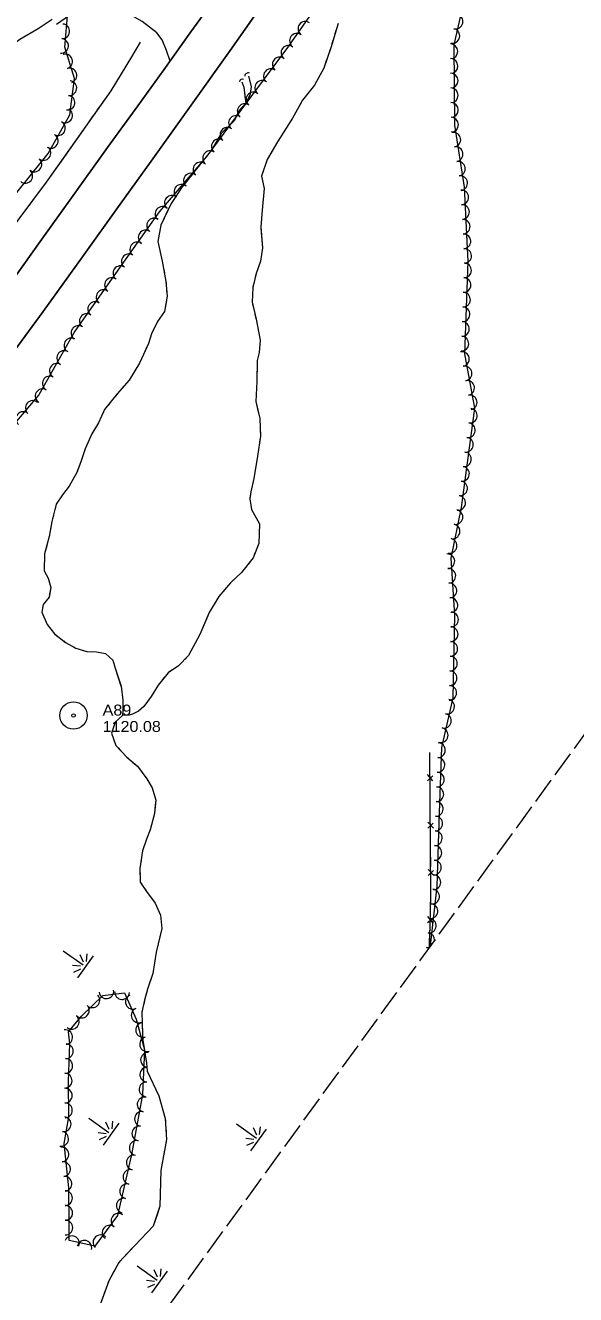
# Model space of a CAD drawing. Extents: x 297327 to 299792, y 46897 to 49095.
# Drawn here: x 298790 to 299091, y 47500 to 48196 of the extents above; entities that cross this region are included whole.
import ezdxf

# ---------------------------------------------------------------- set-up
doc = ezdxf.new("R2010")
doc.units = 0
doc.header["$LTSCALE"] = 2.4
doc.linetypes.add('LONG_DASHED', pattern=[7.5, 6, -1.5])
for name, color, linetype, lineweight in [('11', 7, 'Continuous', 25), ('15', 7, 'Continuous', 13), ('17', 7, 'LONG_DASHED', 13), ('18', 7, 'Continuous', 13), ('19', 7, 'Continuous', 13), ('4', 7, 'Continuous', 13), ('6', 7, 'Continuous', 13)]:
    doc.layers.add(name, color=color, linetype=linetype, lineweight=lineweight)

msp = doc.modelspace()

# ---------------------------------------------------------------- linework, layer by layer
at = {"layer": '11'}
for points in [[(298773.947, 48043.937), (298797.872, 48077.411), (298815.068, 48101.215), (298834.844, 48128.806), (298851.433, 48151.673), (298865.686, 48171.463), (298880.386, 48192.263), (298896.726, 48214.837)], [(298781.415, 48014.255), (298799.539, 48039.023), (298821.048, 48068.955), (298841.741, 48097.8), (298858.666, 48121.374), (298879.721, 48150.861), (298901.899, 48182.138), (298918.424, 48205.473)]]:
    msp.add_lwpolyline(points, dxfattribs=at)
at = {"layer": '15'}
for p, q in [((299011.49, 47786.643), (299011.405, 47797.194)), ((299013.152, 47781.603), (299010.105, 47785.043)), ((299010.132, 47781.737), (299013.066, 47784.367)), ((299011.615, 47771.229), (299011.54, 47780.509)), ((299011.7, 47760.679), (299011.615, 47771.229)), ((299013.362, 47755.639), (299010.315, 47759.078)), ((299010.342, 47755.773), (299013.276, 47758.402)), ((299011.825, 47745.265), (299011.75, 47754.544)), ((299011.91, 47734.714), (299011.825, 47745.265)), ((299013.572, 47729.674), (299010.525, 47733.114)), ((299010.552, 47729.808), (299013.486, 47732.438)), ((299011.728, 47708.753), (299012.022, 47719.3)), ((299010.194, 47703.899), (299013.221, 47706.422)), ((299013.207, 47703.657), (299010.286, 47707.204)), ((299011.271, 47690.502), (299011.338, 47693.344))]:
    msp.add_line(p, q, dxfattribs=at)
for points in [[(299011.271, 47690.502), (299011.545, 47702.188), (299012.032, 47719.673), (299011.405, 47797.194)], [(299012.022, 47719.3), (299012.032, 47719.673), (299011.96, 47728.58)], [(299011.338, 47693.344), (299011.545, 47702.188), (299011.557, 47702.621)]]:
    msp.add_lwpolyline(points, dxfattribs=at)
for centre, radius, start, end in [((298911.845, 48167.881), 1.876, 68.43566, 174.67523), ((298908.683, 48164.735), 1.626, 67.28803, 173.52759)]:
    msp.add_arc(centre, radius, start, end, dxfattribs=at)
at = {"layer": '17'}
for points in [[(298869.073, 48176.256), (298867.134, 48182.115), (298864.799, 48187.957), (298861.825, 48191.745), (298853.755, 48197.965), (298841.935, 48204.811), (298834.747, 48207.957), (298827.75, 48208.774), (298821.748, 48206.38), (298816.292, 48202.905), (298806.831, 48196.299)], [(298804.335, 48199.125), (298796.758, 48194.022), (298786.781, 48188.133), (298778.292, 48181.845), (298770.455, 48177.553)]]:
    msp.add_lwpolyline(points, dxfattribs=at)
at = {"layer": '18'}
for points in [[(299011.795, 47691.222), (299015.435, 47723.842), (299016.736, 47764.31), (299018.061, 47800.007), (299024.133, 47827.15), (299025.206, 47872.392), (299023.037, 47903.737), (299028.711, 47931.468), (299036.04, 47985.928), (299030.647, 48015.786), (299032.488, 48066.369), (299030.517, 48107.23), (299025.207, 48141.127), (299024.814, 48185.103), (299032.807, 48220.691), (299036.611, 48250.046), (299043.903, 48276.662), (299057.908, 48300.748), (299070.384, 48317.762), (299076.733, 48326.492)], [(298948.867, 48205.749), (298933.44, 48183.723), (298907.768, 48149.445), (298889.188, 48124.204), (298863.058, 48093.645), (298844.723, 48067.797), (298816.908, 48028.238), (298797.151, 47993.274), (298775.572, 47968.078)], [(298764.559, 48197.242), (298760.904, 48170.711), (298762.442, 48144.645), (298760.665, 48123.823), (298759.649, 48104.523), (298756.703, 48095.82), (298757.654, 48091.129), (298770.724, 48090.882), (298784.392, 48103.366), (298802.216, 48125.633), (298814.147, 48146.778), (298816.652, 48166.779), (298811.357, 48183.936), (298812.99, 48203.324)]]:
    msp.add_lwpolyline(points, dxfattribs=at)
msp.add_lwpolyline([(298814.192, 47637.368), (298813.318, 47644.049), (298820.452, 47652.591), (298832.182, 47663.884), (298844.16, 47665.439), (298850.429, 47651.003), (298855.11, 47634.11), (298853.896, 47609.629), (298847.959, 47576.761), (298840.282, 47543.394), (298827.783, 47526.519), (298813.673, 47529.645), (298813.759, 47537.868), (298813.561, 47558.415), (298811.04, 47582.814), (298813.583, 47597.512), (298813.402, 47616.899)], close=True, dxfattribs=at)
for centre, radius, start, end in [((298943.188, 48193.988), 4.004, 55.00028, 234.98496), ((299025.533, 48197.91), 4.023, 257.34919, 77.33387), ((298809.977, 48192.584), 4.014, 265.19315, 85.17783), ((298938.594, 48187.429), 4.004, 55.00028, 234.98496), ((299023.77, 48190.061), 4.023, 257.34919, 77.33387), ((298809.303, 48184.585), 4.014, 265.19315, 85.17783), ((298933.91, 48180.854), 4.004, 53.17683, 233.16151), ((299022.739, 48181.649), 4.023, 270.51968, 90.50436), ((298811.577, 48176.1), 4.014, 287.15895, 107.14363), ((298929.11, 48174.445), 4.004, 53.17683, 233.16151), ((299022.811, 48173.605), 4.023, 270.51968, 90.50436), ((298813.944, 48168.43), 4.014, 287.15895, 107.14363), ((298924.31, 48168.036), 4.004, 53.17683, 233.16151), ((299022.883, 48165.561), 4.023, 270.51968, 90.50436), ((298813.865, 48161.433), 4.014, 262.86889, 82.85357), ((298919.51, 48161.627), 4.004, 53.17683, 233.16151), ((298812.868, 48153.468), 4.014, 262.86889, 82.85357), ((298914.71, 48155.218), 4.004, 53.17683, 233.16151), ((299022.955, 48157.517), 4.023, 270.51968, 90.50436), ((298811.556, 48146.462), 4.014, 240.57393, 60.55861), ((298909.91, 48148.809), 4.004, 53.17683, 233.16151), ((299023.027, 48149.473), 4.023, 270.51968, 90.50436), ((298807.612, 48139.471), 4.014, 240.57393, 60.55861), ((298905.168, 48142.378), 4.004, 53.65073, 233.63541), ((299023.099, 48141.429), 4.023, 270.51968, 90.50436), ((298803.667, 48132.48), 4.014, 240.57393, 60.55861), ((298900.421, 48135.929), 4.004, 53.65073, 233.63541), ((299024.322, 48133.171), 4.023, 278.91075, 98.89543), ((298799.732, 48125.891), 4.014, 231.33154, 51.31622), ((298895.675, 48129.481), 4.004, 53.65073, 233.63541), ((299025.567, 48125.224), 4.023, 278.91075, 98.89543), ((298794.716, 48119.625), 4.014, 231.33154, 51.31622), ((298885.634, 48116.823), 4.004, 49.47499, 229.45967), ((298890.928, 48123.032), 4.004, 53.65073, 233.63541), ((299026.812, 48117.277), 4.023, 278.91075, 98.89543), ((298789.699, 48113.358), 4.014, 231.33154, 51.31622), ((298880.43, 48110.737), 4.004, 49.47499, 229.45967), ((298875.227, 48104.651), 4.004, 49.47499, 229.45967), ((299028.057, 48109.329), 4.023, 278.91075, 98.89543), ((298870.023, 48098.566), 4.004, 49.47499, 229.45967), ((299028.683, 48101.546), 4.023, 272.76928, 92.75396), ((298864.819, 48092.48), 4.004, 49.47499, 229.45967), ((299029.071, 48093.511), 4.023, 272.76928, 92.75396), ((298860.284, 48086.113), 4.004, 54.65809, 234.64277), ((299029.459, 48085.476), 4.023, 272.76928, 92.75396), ((298855.652, 48079.582), 4.004, 54.65809, 234.64277), ((299029.846, 48077.441), 4.023, 272.76928, 92.75396), ((298851.019, 48073.051), 4.004, 54.65809, 234.64277), ((299030.234, 48069.406), 4.023, 272.76928, 92.75396), ((298846.392, 48066.527), 4.004, 54.89558, 234.88025), ((299030.206, 48061.547), 4.023, 267.92327, 87.90794), ((298841.786, 48059.976), 4.004, 54.89558, 234.88025), ((298837.18, 48053.426), 4.004, 54.89558, 234.88025), ((299029.913, 48053.508), 4.023, 267.92327, 87.90794), ((298827.969, 48040.326), 4.004, 54.89558, 234.88025), ((298832.575, 48046.876), 4.004, 54.89558, 234.88025), ((299029.621, 48045.469), 4.023, 267.92327, 87.90794), ((298823.364, 48033.776), 4.004, 54.89558, 234.88025), ((299029.328, 48037.43), 4.023, 267.92327, 87.90794), ((298818.758, 48027.226), 4.004, 54.89558, 234.88025), ((299029.035, 48029.391), 4.023, 267.92327, 87.90794), ((298814.909, 48020.441), 4.004, 60.53831, 240.52298), ((299028.743, 48021.352), 4.023, 267.92327, 87.90794), ((298810.97, 48013.47), 4.004, 60.53831, 240.52298), ((299029.029, 48012.902), 4.023, 280.24613, 100.23081), ((298807.031, 48006.499), 4.004, 60.53831, 240.52298), ((298803.092, 47999.528), 4.004, 60.53831, 240.52298), ((299030.458, 48004.986), 4.023, 280.24613, 100.23081), ((298799.153, 47992.556), 4.004, 60.53831, 240.52298), ((299031.888, 47997.069), 4.023, 280.24613, 100.23081), ((298793.768, 47986.102), 4.004, 49.42941, 229.41409), ((299033.318, 47989.153), 4.023, 280.24613, 100.23081), ((298788.56, 47980.021), 4.004, 49.42941, 229.41409), ((299033.368, 47981.862), 4.023, 262.34308, 82.32776), ((299032.296, 47973.889), 4.023, 262.34308, 82.32776), ((299031.223, 47965.917), 4.023, 262.34308, 82.32776), ((299030.15, 47957.945), 4.023, 262.34308, 82.32776), ((299029.077, 47949.972), 4.023, 262.34308, 82.32776), ((299028.004, 47942), 4.023, 262.34308, 82.32776), ((299026.931, 47934.028), 4.023, 262.34308, 82.32776), ((299025.497, 47926.262), 4.023, 258.44406, 78.42874), ((299023.884, 47918.381), 4.023, 258.44406, 78.42874), ((299022.272, 47910.5), 4.023, 258.44406, 78.42874), ((299021.045, 47902.023), 4.023, 273.96608, 93.95076), ((299021.6, 47893.998), 4.023, 273.96608, 93.95076), ((299022.156, 47885.973), 4.023, 273.96608, 93.95076), ((299022.711, 47877.948), 4.023, 273.96608, 93.95076), ((299023.046, 47870.114), 4.023, 268.64904, 88.63372), ((299022.855, 47862.072), 4.023, 268.64904, 88.63372), ((299022.665, 47854.03), 4.023, 268.64904, 88.63372), ((299022.474, 47845.988), 4.023, 268.64904, 88.63372), ((299022.283, 47837.946), 4.023, 268.64904, 88.63372), ((299022.092, 47829.904), 4.023, 268.64904, 88.63372), ((299020.913, 47822.399), 4.023, 257.39797, 77.38265), ((299019.157, 47814.549), 4.023, 257.39797, 77.38265), ((299017.401, 47806.699), 4.023, 257.39797, 77.38265), ((299015.896, 47798.428), 4.023, 267.88194, 87.86661), ((299015.597, 47790.389), 4.023, 267.88194, 87.86661), ((299015.299, 47782.351), 4.023, 267.88194, 87.86661), ((299015, 47774.312), 4.023, 267.88194, 87.86661), ((299014.702, 47766.273), 4.023, 267.88194, 87.86661), ((299014.434, 47758.223), 4.023, 268.1663, 88.15098), ((299014.175, 47750.183), 4.023, 268.1663, 88.15098), ((299013.917, 47742.143), 4.023, 268.1663, 88.15098), ((299013.658, 47734.103), 4.023, 268.1663, 88.15098), ((299013.4, 47726.063), 4.023, 268.1663, 88.15098), ((299012.689, 47718.222), 4.023, 263.64058, 83.62526), ((299011.797, 47710.227), 4.023, 263.64058, 83.62526), ((299010.905, 47702.233), 4.023, 263.64058, 83.62526), ((299010.013, 47694.238), 4.023, 0.91146, 83.62526), ((299010.013, 47694.238), 4.023, 263.64058, 287.03077), ((299009.121, 47686.244), 4.023, 64.94569, 83.62526), ((298826.491, 47661.341), 4.041, 223.92026, 43.90494), ((298834.11, 47666.267), 4.041, 187.40451, 7.38919), ((298842.756, 47665.841), 4.041, 177.40451, 357.38919), ((298848.611, 47660.5), 4.041, 113.48112, 293.46579), ((298820.669, 47655.736), 4.041, 223.92026, 43.90494), ((298851.83, 47653.087), 4.041, 113.48112, 293.46579), ((298815.146, 47649.538), 4.041, 230.14013, 50.12481), ((298854.264, 47645.084), 4.041, 105.49556, 285.48023), ((298811.57, 47641.101), 4.041, 277.4607, 97.44538), ((298856.422, 47637.296), 4.041, 105.49556, 285.48023), ((298811.923, 47633.412), 4.041, 267.79743, 87.78211), ((298811.611, 47625.337), 4.041, 267.79743, 87.78211), ((298856.957, 47628.65), 4.041, 87.16872, 267.1534), ((298811.299, 47617.261), 4.041, 267.79743, 87.78211), ((298856.557, 47620.578), 4.041, 87.16872, 267.1534), ((298811.36, 47609.078), 4.041, 270.54257, 90.52725), ((298856.156, 47612.506), 4.041, 87.16872, 267.1534), ((298855.072, 47604.238), 4.041, 79.76864, 259.75332), ((298811.435, 47600.997), 4.041, 270.54257, 90.52725), ((298853.635, 47596.285), 4.041, 79.76864, 259.75332), ((298810.719, 47593.363), 4.041, 260.19171, 80.17639), ((298852.198, 47588.332), 4.041, 79.76864, 259.75332), ((298809.341, 47585.399), 4.041, 260.19171, 80.17639), ((298809.535, 47576.804), 4.041, 275.90675, 95.89143), ((298850.762, 47580.379), 4.041, 79.76864, 259.75332), ((298810.365, 47568.765), 4.041, 275.90675, 95.89143), ((298849.118, 47572.366), 4.041, 77.05067, 257.03535), ((298811.196, 47560.726), 4.041, 275.90675, 95.89143), ((298847.306, 47564.49), 4.041, 77.05067, 257.03535), ((298845.494, 47556.614), 4.041, 77.05067, 257.03535), ((298811.499, 47552.855), 4.041, 270.55977, 90.54445), ((298843.682, 47548.738), 4.041, 77.05067, 257.03535), ((298811.577, 47544.773), 4.041, 270.55977, 90.54445), ((298840.725, 47540.439), 4.041, 53.481, 233.46568), ((298811.632, 47536.735), 4.041, 269.40846, 89.39314), ((298835.915, 47533.944), 4.041, 53.481, 233.46568), ((298815.338, 47528.096), 4.041, 337.51584, 157.50051), ((298822.096, 47525.613), 4.041, 347.51584, 167.50051), ((298830.895, 47528.647), 4.041, 43.481, 223.46568)]:
    msp.add_arc(centre, radius, start, end, dxfattribs=at)
at = {"layer": '19'}
for p, q in [((298959.977, 48192.979), (298959.435, 48191.183)), ((298958.349, 48187.589), (298957.806, 48185.793)), ((298956.677, 48182.214), (298956.074, 48180.437)), ((298912.505, 48157.25), (298912.215, 48156.642)), ((298829.146, 48149.292), (298830.234, 48150.823)), ((298832.411, 48153.887), (298833.499, 48155.418)), ((298911.637, 48155.425), (298911.349, 48154.816)), ((298888.958, 48123.914), (298887.769, 48122.434)), ((298925.106, 48127.141), (298924.175, 48125.511)), ((298920.503, 48116.921), (298919.9, 48115.143)), ((298791.988, 48097.338), (298793.116, 48098.84)), ((298865.572, 48061.982), (298865.915, 48060.116)), ((298914.901, 48054.241), (298914.477, 48052.413)), ((298867.176, 48050.723), (298867.339, 48048.833)), ((298914.246, 48048.673), (298914.161, 48046.798)), ((298914.302, 48043.077), (298914.731, 48041.25)), ((298836.405, 47989.299), (298835.213, 47987.822)), ((298839.981, 47993.73), (298838.789, 47992.253)), ((298832.922, 47984.811), (298832.135, 47983.084)), ((298918.256, 47980.147), (298918.32, 47978.272)), ((298918.45, 47974.522), (298918.514, 47972.647)), ((298918.336, 47968.915), (298918.072, 47967.059)), ((298805.126, 47927.113), (298804.657, 47925.275)), ((298803.894, 47921.559), (298803.567, 47919.69)), ((298915.867, 47907.23), (298915.19, 47905.48)), ((298913.307, 47902.282), (298912.142, 47900.81)), ((298909.812, 47897.867), (298908.647, 47896.396)), ((298815.625, 47855.405), (298817.274, 47854.465)), ((298820.901, 47853.355), (298822.717, 47852.806)), ((298865.974, 47838.44), (298864.801, 47836.974)), ((298870.019, 47842.256), (298868.452, 47841.223)), ((298838.01, 47804.712), (298838.65, 47802.925)), ((298840.562, 47799.739), (298841.864, 47798.358)), ((298853.178, 47738.02), (298852.876, 47736.146)), ((298852.517, 47732.383), (298852.582, 47730.486)), ((298810.524, 47688.505), (298821.437, 47680.695)), ((298818.457, 47673.697), (298827.068, 47685.728)), ((298821.643, 47682.306), (298819.792, 47686.336)), ((298823.488, 47686.869), (298823.043, 47682.656)), ((298820.01, 47680.025), (298815.599, 47680.477)), ((298816.286, 47676.806), (298820.13, 47678.586)), ((298856.484, 47666.5), (298856.002, 47664.665)), ((298855.047, 47660.992), (298854.624, 47659.142)), ((298824.601, 47596.668), (298835.514, 47588.858)), ((298832.534, 47581.86), (298841.145, 47593.891)), ((298835.72, 47590.469), (298833.869, 47594.499)), ((298837.565, 47595.032), (298837.12, 47590.819)), ((298905.445, 47593.522), (298916.358, 47585.712)), ((298918.409, 47591.886), (298917.964, 47587.673)), ((298834.087, 47588.188), (298829.676, 47588.64)), ((298830.363, 47584.969), (298834.207, 47586.749)), ((298866.709, 47591.131), (298866.834, 47589.12)), ((298914.931, 47585.042), (298910.52, 47585.494)), ((298913.378, 47578.714), (298921.989, 47590.745)), ((298916.564, 47587.323), (298914.713, 47591.353)), ((298866.005, 47579.154), (298865.632, 47577.174)), ((298911.207, 47581.823), (298915.051, 47583.603)), ((298851.044, 47515.671), (298861.957, 47507.861)), ((298838.682, 47513.54), (298837.718, 47511.771)), ((298858.977, 47500.863), (298867.588, 47512.894)), ((298862.163, 47509.472), (298860.312, 47513.502)), ((298864.008, 47514.035), (298863.563, 47509.822)), ((298860.53, 47507.191), (298856.119, 47507.643)), ((298856.806, 47503.972), (298860.65, 47505.752))]:
    msp.add_line(p, q, dxfattribs=at)
for points in [[(298961.166, 48196.914), (298957.122, 48183.527), (298953.349, 48172.398), (298948.134, 48163.049), (298941.658, 48154.796), (298936.091, 48144.931), (298927.903, 48132.038), (298922.307, 48122.241), (298919.24, 48113.196), (298920.657, 48106.386), (298919.559, 48094.527), (298918.758, 48085.315), (298919.637, 48073.95), (298918.579, 48066.538), (298916.205, 48059.868), (298914.4, 48052.082), (298914.043, 48044.182), (298916.269, 48034.69), (298918.439, 48023.341), (298917.817, 48016.561), (298916.742, 48012.124), (298916.636, 48000.545), (298916.044, 47989.559), (298918.248, 47980.371), (298918.583, 47970.651), (298917.019, 47959.657), (298914.987, 47947.399), (298913.316, 47940.076), (298912.79, 47936.272), (298913.754, 47930.404), (298918.092, 47922.587), (298917.63, 47911.783), (298914.568, 47903.874), (298908.26, 47895.907), (298902.082, 47890.288), (298895.796, 47882.643), (298890.525, 47873.964), (298885.436, 47861.934), (298879.227, 47850.315), (298873.748, 47844.714), (298867.919, 47840.872), (298862.534, 47834.139), (298858.754, 47827.857), (298854.614, 47822.472), (298851.818, 47819.77), (298848.434, 47818.172), (298846.706, 47817.722), (298842.921, 47817.431)], [(298503.742, 47697.478), (298514.812, 47710.941), (298526.649, 47726.155), (298534.399, 47737.656), (298546.205, 47756.567), (298562.394, 47777.388), (298582.54, 47805.6), (298602.679, 47834.157), (298623.553, 47862.124), (298639.747, 47887.514), (298653.06, 47906.486), (298670.901, 47932.218), (298687.983, 47957.11), (298704.974, 47979.962), (298727.406, 48011.113), (298744.717, 48035.236), (298760.985, 48057.025), (298778.27, 48079.067), (298801.383, 48109.85), (298823.913, 48141.926), (298836.751, 48159.996), (298848.108, 48178.546), (298852.756, 48186.566)], [(298838.724, 48163.218), (298848.108, 48178.546), (298852.756, 48186.566)], [(298954.869, 48176.883), (298953.349, 48172.398), (298948.134, 48163.049), (298941.658, 48154.796), (298941.031, 48153.686)], [(298912.085, 48168.038), (298913.548, 48162.397), (298912.94, 48158.158), (298911.966, 48156.123), (298910.692, 48153.425), (298910.035, 48159.045), (298909.689, 48161.876), (298908.588, 48164.762)], [(298910.48, 48155.243), (298910.035, 48159.045), (298909.689, 48161.876), (298908.588, 48164.762)], [(298912.085, 48168.038), (298913.548, 48162.397), (298912.988, 48158.495)], [(298835.675, 48158.481), (298836.751, 48159.996), (298836.762, 48160.014)], [(298910.692, 48153.425), (298906.694, 48148.912), (298904.34, 48143.631), (298897.036, 48136.476), (298891.761, 48127.401), (298884.255, 48118.063), (298875.626, 48107.289), (298869.731, 48098.145), (298863.978, 48086.32), (298862.251, 48077.283), (298864.746, 48066.481), (298866.766, 48055.481), (298867.472, 48047.297), (298865.967, 48039.064), (298862.103, 48033.535), (298858.926, 48026.787), (298857.234, 48021.406), (298854.414, 48015.365), (298852.225, 48010.582), (298846.675, 48001.324), (298840.065, 47993.834), (298833.102, 47985.207), (298829.825, 47978.012), (298826.09, 47971.855), (298822.44, 47963.612), (298820.235, 47957.052), (298818.032, 47950.651), (298813.815, 47943.273), (298810.073, 47938.425), (298806.697, 47933.267), (298804.303, 47923.89), (298802.856, 47915.638), (298800.23, 47906.043), (298800.03, 47896.863), (298802.178, 47892.833), (298803.73, 47887.64), (298802.75, 47882.427), (298799.417, 47878.344), (298798.801, 47874.099), (298801.636, 47867.377), (298805.689, 47862.272), (298811.81, 47857.583), (298817.324, 47854.436), (298823.516, 47852.565), (298828.73, 47852.429), (298833.727, 47851.51), (298837.598, 47847.732), (298838.869, 47843.409), (298842.184, 47833.555), (298843.144, 47825.815), (298843.163, 47820.559), (298842.921, 47817.431), (298838.991, 47813.764), (298836.904, 47807.8), (298839.318, 47801.06), (298845.321, 47794.688), (298851.145, 47789.682), (298856.328, 47782.725), (298859.239, 47777.88), (298861.276, 47771.037), (298860.482, 47763.787), (298858.056, 47754.764), (298856.163, 47749.746), (298854.01, 47743.184), (298852.473, 47733.647), (298852.731, 47726.174), (298856.183, 47721.023), (298860.921, 47714.644), (298863.887, 47708.04), (298864.609, 47700.608), (298861.374, 47687.722), (298859.692, 47676.012), (298856.734, 47667.452), (298855.123, 47661.322), (298853.632, 47654.81), (298853.908, 47642.423), (298854.086, 47639.422), (298856.174, 47626.931), (298856.47, 47622.438)], [(298910.692, 48153.425), (298906.694, 48148.912), (298904.34, 48143.631), (298897.036, 48136.476), (298894.282, 48131.737)], [(298910.774, 48153.598), (298910.692, 48153.425), (298910.636, 48153.904)], [(298941.031, 48153.686), (298936.091, 48144.931), (298927.903, 48132.038), (298926.967, 48130.4)], [(298811.288, 48123.951), (298823.913, 48141.926), (298826.97, 48146.229)], [(298892.374, 48128.455), (298891.761, 48127.401), (298891.336, 48126.872)], [(298795.372, 48101.845), (298801.383, 48109.85), (298811.288, 48123.951)], [(298922.313, 48122.252), (298922.307, 48122.241), (298921.708, 48120.475)], [(298881.829, 48115.034), (298875.626, 48107.289), (298869.731, 48098.145), (298866.792, 48092.104)], [(298885.391, 48119.476), (298884.255, 48118.063), (298884.202, 48117.996)], [(298919.586, 48111.535), (298920.657, 48106.386), (298919.559, 48094.527), (298918.758, 48085.315), (298918.819, 48084.52)], [(298866.792, 48092.104), (298863.978, 48086.32), (298862.251, 48077.283), (298864.746, 48066.481), (298864.887, 48065.715)], [(298918.819, 48084.52), (298919.637, 48073.95), (298918.579, 48066.538), (298916.205, 48059.868), (298915.748, 48057.896)], [(298866.6, 48056.382), (298866.766, 48055.481), (298866.85, 48054.504)], [(298867.067, 48045.081), (298865.967, 48039.064), (298862.103, 48033.535), (298858.926, 48026.787), (298857.234, 48021.406), (298856.584, 48020.013)], [(298915.588, 48037.596), (298916.269, 48034.69), (298918.439, 48023.341), (298917.817, 48016.561), (298916.742, 48012.124), (298916.73, 48010.831)], [(298856.584, 48020.013), (298854.414, 48015.365), (298852.225, 48010.582), (298846.675, 48001.324), (298842.488, 47996.58)], [(298916.73, 48010.831), (298916.636, 48000.545), (298916.044, 47989.559), (298917.425, 47983.803)], [(298830.562, 47979.63), (298829.825, 47978.012), (298826.09, 47971.855), (298822.44, 47963.612), (298820.235, 47957.052), (298819.389, 47954.593)], [(298917.544, 47963.346), (298917.019, 47959.657), (298914.987, 47947.399), (298913.316, 47940.076), (298912.842, 47936.645)], [(298819.389, 47954.593), (298818.032, 47950.651), (298813.815, 47943.273), (298810.073, 47938.425), (298806.697, 47933.267), (298806.065, 47930.791)], [(298912.842, 47936.645), (298912.79, 47936.272), (298913.754, 47930.404), (298918.092, 47922.587), (298917.63, 47911.783), (298917.223, 47910.731)], [(298802.911, 47915.952), (298802.856, 47915.638), (298802.439, 47914.115)], [(298801.437, 47910.454), (298800.23, 47906.043), (298800.03, 47896.863), (298802.178, 47892.833), (298803.73, 47887.64), (298803.032, 47883.93)], [(298905.945, 47893.801), (298902.082, 47890.288), (298895.796, 47882.643), (298890.525, 47873.964), (298889.769, 47872.178)], [(298803.032, 47883.93), (298802.75, 47882.427), (298799.417, 47878.344), (298798.801, 47874.099), (298801.636, 47867.377), (298805.689, 47862.272), (298807.764, 47860.682)], [(298889.769, 47872.178), (298885.436, 47861.934), (298879.227, 47850.315), (298877.187, 47848.23)], [(298810.777, 47858.374), (298811.81, 47857.583), (298812.329, 47857.287)], [(298826.476, 47852.488), (298828.73, 47852.429), (298833.727, 47851.51), (298837.598, 47847.732), (298838.869, 47843.409), (298842.143, 47833.678)], [(298874.562, 47845.547), (298873.748, 47844.714), (298873.153, 47844.322)], [(298842.143, 47833.678), (298842.184, 47833.555), (298843.144, 47825.815), (298843.163, 47820.559), (298842.921, 47817.431), (298838.991, 47813.764), (298837.074, 47808.287)], [(298862.471, 47834.034), (298858.754, 47827.857), (298854.614, 47822.472), (298851.818, 47819.77), (298848.434, 47818.172), (298846.706, 47817.722), (298842.921, 47817.431)], [(298844.467, 47795.595), (298845.321, 47794.688), (298845.816, 47794.263)], [(298848.694, 47791.789), (298851.145, 47789.682), (298856.328, 47782.725), (298859.239, 47777.88), (298861.276, 47771.037), (298860.969, 47768.233)], [(298860.969, 47768.233), (298860.482, 47763.787), (298858.056, 47754.764), (298856.163, 47749.746), (298854.01, 47743.184), (298853.782, 47741.767)], [(298852.713, 47726.692), (298852.731, 47726.174), (298853.499, 47725.028)], [(298855.612, 47721.875), (298856.183, 47721.023), (298860.921, 47714.644), (298863.887, 47708.04), (298864.609, 47700.608), (298863.673, 47696.881)], [(298863.673, 47696.881), (298861.374, 47687.722), (298859.692, 47676.012), (298857.652, 47670.109)], [(298853.777, 47655.443), (298853.632, 47654.81), (298853.66, 47653.562)], [(298853.744, 47649.767), (298853.908, 47642.423), (298854.086, 47639.422), (298856.174, 47626.931), (298856.47, 47622.438)], [(298856.47, 47622.438), (298862.814, 47608.969), (298866.377, 47596.465), (298867.095, 47584.937), (298863.901, 47567.991), (298863.47, 47548.37), (298859.834, 47537.481), (298849.775, 47526.923), (298840.874, 47517.564), (298835.411, 47507.537), (298830.295, 47493.442), (298825.658, 47477.877), (298822.145, 47464.56), (298818.645, 47452.401), (298813.336, 47441.178), (298807.387, 47425.507), (298801.758, 47412.038), (298798.463, 47400.49), (298798.326, 47397.719)], [(298856.47, 47622.438), (298862.814, 47608.969), (298866.377, 47596.465), (298866.459, 47595.154)], [(298867.085, 47585.097), (298867.095, 47584.937), (298866.751, 47583.114)], [(298864.885, 47573.213), (298863.901, 47567.991), (298863.47, 47548.37), (298862.114, 47544.31)], [(298862.114, 47544.31), (298859.834, 47537.481), (298849.775, 47526.923), (298844.657, 47521.541)], [(298841.881, 47518.623), (298840.874, 47517.564), (298840.609, 47517.078)], [(298833.619, 47502.601), (298830.295, 47493.442), (298825.658, 47477.877), (298824.835, 47474.756)], [(298835.79, 47508.233), (298835.411, 47507.537), (298834.994, 47506.389)]]:
    msp.add_lwpolyline(points, dxfattribs=at)
at = {"layer": '4', "linetype": 'LONG_DASHED'}
msp.add_line((299321.306, 48116.776), (298695.48, 47256.313), dxfattribs=at)
at = {"layer": '6'}
for radius in [7.5, 0.96]:
    msp.add_circle((298816.078, 47817.449), radius, dxfattribs=at)

# ---------------------------------------------------------------- texts
at = {"layer": '6', "width": 1.1}
for s, p in [('A89', (298832.078, 47817.449)), ('1120.08', (298832.078, 47808.449))]:
    msp.add_text(s, height=6, dxfattribs=at).set_placement(p)

doc.saveas('drawing.dxf')
